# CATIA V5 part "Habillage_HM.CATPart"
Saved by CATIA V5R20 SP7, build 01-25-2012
Part number: Habillage_HM
Bounding box of the stored display mesh (mm): x -4.1 to 0, y -3 to 3, z -12.353 to 28.353
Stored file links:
  F:\IAO\Catia\Habillage_HM.CATPart
  F:\IAO\Catia\asandre.CATProduct
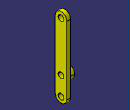
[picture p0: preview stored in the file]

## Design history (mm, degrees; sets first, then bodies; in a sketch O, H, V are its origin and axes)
Set1
  Plane1 "plan.-2": linked copy from another document
  Point1 "M": linked copy from another document
  Point2 "H": linked copy from another document
  Point3 "K": linked copy from another document
Body1 (main body)
  Sketch1 "Bielle_HM" on Plane1, origin (-2, 0, 0), H (0, 1, 0), V (0, 0, 1)
    construction line L1 (0, 25.5) -> (0, -9.5)
    point P1 (0, 25.5)
    point P2 (0, -9.5)
    line L2 (3, 25.5) -> (3, -9.5)
    line L3 (-3, -9.5) -> (-3, 25.5)
    arc A1 centre (0, -9.5) radius 3 from (3, -9.5) to (-3, -9.5) cw
    arc A2 centre (0, 25.5) radius 3 from (-3, 25.5) to (3, 25.5) cw
    reference projected point E1 (0, 25.5) from Point1
    reference projected point E2 (0, -9.5) from Point2
    circle A3 centre (0, 25.5) radius 1.5
    point P7 (0, 25.5)
    reference projected point E3 (0, 25.5) from Point1
    circle A4 centre (0, 0) radius 1.5
    point P8 (0, 0)
    reference projected point E4 (0, 0) from Point3
    circle A5 centre (0, -9.5) radius 1.5
    point P9 (0, -9.5)
    reference projected point E5 (0, -9.5) from Point2
    distance L1 L2 = 3
    radius A3 = 1.5
    radius A4 = 1.5
    radius A5 = 1.5
    tangency: A1 L2, A2 L2, A1 L3, A2 L3
    coincidence: P1 E1, P2 E2, P7 E3, P8 E4, P9 E5
  Pad1 "Bielle_HM": profile Sketch1, direction (1, 0, 0), length 2
  Sketch2 "Pivot.K" on Plane1, origin (-2, 0, 0), H (0, 1, 0), V (0, 0, 1)
    circle A1 centre (0, 0) radius 3
    point P1 (0, 0)
    reference projected point E1 (0, 0) from Point3
    radius A1 = 3
    coincidence: P1 E1
  Pad2 "Pivot.K": profile Sketch2, direction (-1, 0, 0), length 2.1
